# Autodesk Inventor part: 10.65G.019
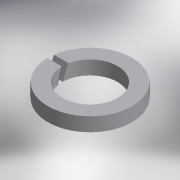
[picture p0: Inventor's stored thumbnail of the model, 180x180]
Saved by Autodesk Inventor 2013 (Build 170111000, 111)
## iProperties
Shininess: 25.0
Length Units: 11269
Angle Units: 11279
Time Units: 11290
Mass Units: 11283
Length Display Precision: 3
Angle Display Precision: 2
Created: 2001-04
Material: Steel, Mild
Description: Шайба 10.65Г.019 ГОСТ 6402-70
Document SubType Name: Modeling
Designer: tevgeniy
Mass: 1.96654 g
Surface Area: 4.06504 cm^2
Volume: 0.250196 cm^3
Density: 7.86 g/cm^3
Density: 7.86
Volumn: 0.2501956736428592
Area: 4.065041569612211
PropertySet Name: Model Information
Control State: 0
Master: False
Checked Out: False
Last Check In Date: 2008-10-15
Checked Out Date: 2008-10-15
Author: tevgeniy
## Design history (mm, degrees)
node "ExtrusionBlind1" dims "d2" = 2.5, "d3" = 0
  sketch "Sketch1"
    geometry: C1 r 7.6 at (-266.435, -313.047)
    constraints: 1 centre point, 1 other
    dimensions: "d1" = 15.2 diameter of C1
node "Hole1" dims "d5" = 10, "d6" = 4, "d7" = 2, "d8" = 60 deg, "d9" = 8, "d10" = 118 deg
  sketch "Sketch2"
    geometry: C1 r 7.6 at (0, 0) reference
node "WorkPlane1"
node "ExtrusionToFace1" dims "d18" = 0.13, "d19" = 0
  sketch "Sketch3"
    geometry: L1 (-21.641, 0.09)-(-21.641, -1); L2 (-19.141, 1)-(-21.641, 0.09); L3 (-19.141, -0.09)-(-19.141, 1); L4 (-21.641, -1)-(-19.141, -0.09); L5 (-9.571, 0)-(-31.211, 0); C1 r 7.6 at (-19.141, 0); C2 r 7.6 at (-21.641, 0)
    constraints: 10 end point, 2 centre point, 2 parallel, 1 vertical
    dimensions: "d13" = 0 horizontal distance of L2.start C1.centre; "d15" = 0 horizontal distance of L1.start C2.centre; "d17" = 160 deg angle of L4 L5
body "Solid1"
other parameters: "d0" = 15.2 (derived), "d4" = 0, "d12" = 0 (derived), "d14" = 0 (derived), "d16" = 160 deg (derived), "d20" = 0
